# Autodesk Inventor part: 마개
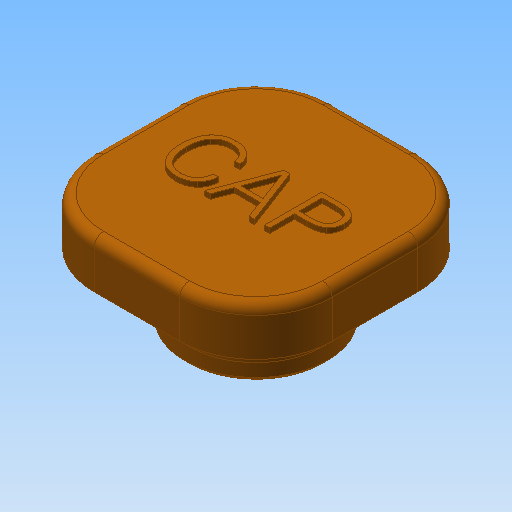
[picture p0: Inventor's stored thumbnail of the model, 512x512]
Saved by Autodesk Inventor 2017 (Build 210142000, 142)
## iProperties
Created: 2018-03
Part Number: 마개
Material: 고무
Document SubType Name: Modeling
Designer: mduedu
Density: 1 g/cm^3
Appearance: 주황색
Author: mduedu
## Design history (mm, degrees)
sketch "스케치1"
  geometry: L1 (12.5, 12.5)-(-12.5, 12.5); L2 (-12.5, 12.5)-(-12.5, -12.5); L3 (-12.5, -12.5)-(12.5, -12.5); L4 (12.5, -12.5)-(12.5, 12.5); L5 (12.5, 12.5)-(-12.5, -12.5); L6 (-12.5, 12.5)-(12.5, -12.5); 1 further point
  constraints: 12 end point, 2 midpoint, 2 parallel, 1 horizontal, 1 perpendicular
  dimensions: "d0" = 25 distance of L3.end L2.end; "d1" = 25 distance of L2.end L1.end
extrude "돌출1" new body sketch "스케치1" distance "d2" = 6; taper "d3" = 0 deg
fillet "모깎기1" dims "d4" = 8
fillet "모깎기2" dims "d5" = 1
sketch "스케치2"
  geometry: L1 (4.5, -12.5)-(-4.5, -12.5) reference; L2 (12.5, 4.5)-(12.5, -4.5) reference; L3 (-4.5, 12.5)-(4.5, 12.5) reference; L4 (-12.5, -4.5)-(-12.5, 4.5) reference; L5 (0, -12.5)-(0, 12.5); L6 (-12.5, 0)-(12.5, 0); C1 r 7.5 at (0, 0); A1 r 8 centre (-4.5, -4.5) between (-12.5, -4.5) and (-4.5, -12.5) reference; A2 r 8 centre (4.5, -4.5) between (4.5, -12.5) and (12.5, -4.5) reference; A3 r 8 centre (4.5, 4.5) between (12.5, 4.5) and (4.5, 12.5) reference; A4 r 8 centre (-4.5, 4.5) between (-4.5, 12.5) and (-12.5, 4.5) reference
  constraints: 5 midpoint, 4 end point, 1 centre point
  dimensions: "d21" = 15 diameter of C1
extrude "돌출2" join sketch "스케치2" distance "d7" = 6; taper "d8" = 0 deg
sketch "스케치3"
  geometry: L1 (4.5, 7.5)-(-4.5, 7.5) reference; L2 (-7.5, 4.5)-(-7.5, -4.5) reference; L3 (-4.5, -7.5)-(4.5, -7.5) reference; L4 (7.5, -4.5)-(7.5, 4.5) reference; C1 r 5.5 at (0, 0); A1 r 3 centre (4.5, 4.5) between (7.5, 4.5) and (4.5, 7.5) reference; A2 r 3 centre (-4.5, 4.5) between (-4.5, 7.5) and (-7.5, 4.5) reference; A3 r 3 centre (-4.5, -4.5) between (-7.5, -4.5) and (-4.5, -7.5) reference; A4 r 3 centre (4.5, -4.5) between (4.5, -7.5) and (7.5, -4.5) reference; 2 further points
  constraints: 1 centre point, 1 vertical alignment
  dimensions: "d22" = 2 dimension on C1
extrude "돌출3" cut sketch "스케치3" stored distance "d10" = 10; taper "d11" = 0 deg
fillet "모깎기3" dims "d12" = 1
sketch "스케치4"
  geometry: L1 (4.5, -12.5)-(-4.5, -12.5) reference; L2 (12.5, 4.5)-(12.5, -4.5) reference; L3 (-4.5, 12.5)-(4.5, 12.5) reference; L4 (-12.5, -4.5)-(-12.5, 4.5) reference; L5 (11.5, 4.5)-(11.5, -4.5); L6 (4.5, -11.5)-(-4.5, -11.5); L7 (-11.5, -4.5)-(-11.5, 4.5); L8 (-4.5, 11.5)-(4.5, 11.5); A1 r 8 centre (-4.5, -4.5) between (-12.5, -4.5) and (-4.5, -12.5) reference; A2 r 8 centre (4.5, -4.5) between (4.5, -12.5) and (12.5, -4.5) reference; A3 r 8 centre (4.5, 4.5) between (12.5, 4.5) and (4.5, 12.5) reference; A4 r 8 centre (-4.5, 4.5) between (-4.5, 12.5) and (-12.5, 4.5) reference; A5 r 7 centre (4.5, 4.5) between (11.5, 4.5) and (4.5, 11.5); A6 r 7 centre (4.5, -4.5) between (4.5, -11.5) and (11.5, -4.5); A7 r 7 centre (-4.5, -4.5) between (-11.5, -4.5) and (-4.5, -11.5); A8 r 7 centre (-4.5, 4.5) between (-4.5, 11.5) and (-11.5, 4.5); 1 further point
  constraints: 8 end point, 8 point on circle, 4 centre point, 7 other
  dimensions: "d13" = 1 distance between parallel lines of L8 L3
extrude "돌출4" cut sketch "스케치4" distance "d14" = 1; taper "d15" = 0 deg
chamfer "모따기1" distance "d16" = 0.5; stored, may be unused: second distance "d17" = 2, angle "d18" = 45 deg
sketch "스케치5"
  geometry: 2 further points
  constraints: 1 coincident, 1 other
feature "엠보싱1" sketch "스케치5" dims "d0" = 25, "d1" = 25, "d19" = 0.5, "d20" = 0
fillet "모깎기4" dims "d23" = 0.5
node "솔리드1"
node "투영된 루프1"
node "투영된 루프2"
node "투영된 루프3"
node "참조1"
